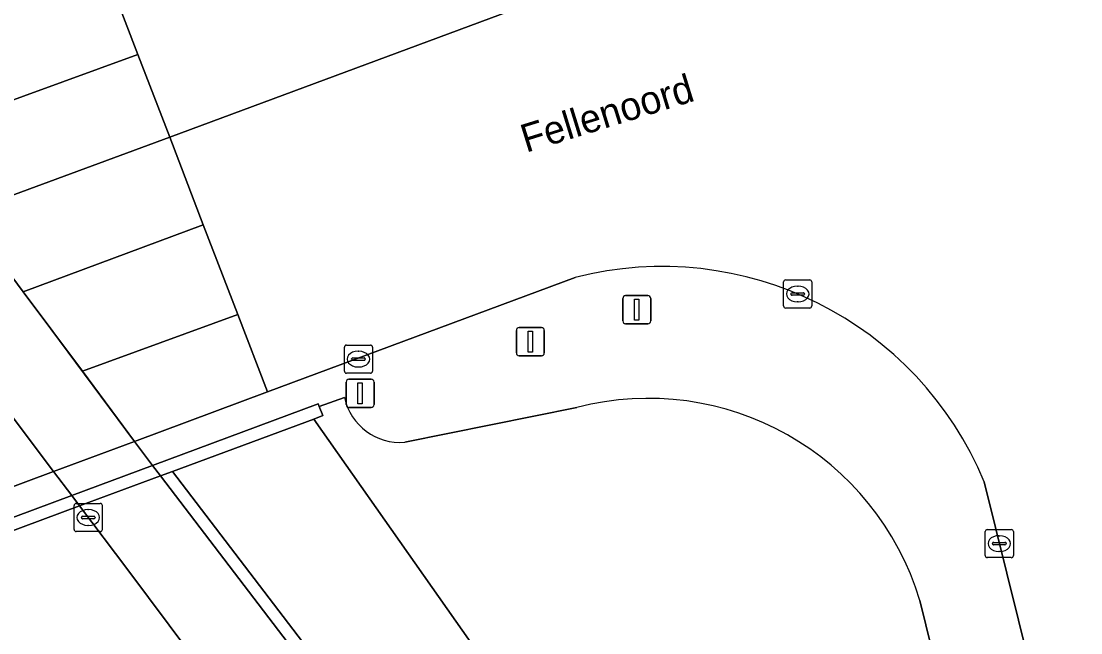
# Model space of a CAD drawing. Extents: x 160806 to 161707, y 383696 to 384148.
# Drawn here: x 160918.71 to 160956.33, y 383784.83 to 383806.57 of the extents above; entities that cross this region are included whole.
import ezdxf

# ---------------------------------------------------------------- set-up
doc = ezdxf.new("R2010")
doc.units = 0
for name, color, linetype in [('IMGEO_Fietspad_open', 7, 'Continuous'), ('IMGEO_Groenvoorziening', 7, 'Continuous'), ('IMGEO_Kolk', 7, 'Continuous'), ('IMGEO_Lichtmast', 7, 'Continuous'), ('IMGEO_Muur', 7, 'Continuous'), ('IMGEO_Openbare_ruimte_label', 7, 'Continuous'), ('IMGEO_Portaal', 7, 'Continuous'), ('IMGEO_Rijbaan_lokaal_gesloten', 7, 'Continuous'), ('IMGEO_Tunneldeel', 7, 'Continuous'), ('IMGEO_Verkeersregelinstallatiepaal', 7, 'Continuous'), ('IMGEO_Voetpad_open', 7, 'Continuous')]:
    doc.layers.add(name, color=color, linetype=linetype)

msp = doc.modelspace()

# ---------------------------------------------------------------- linework, layer by layer
at = {"layer": 'IMGEO_Fietspad_open'}
msp.add_lwpolyline([(160913.472, 383786.627), (160920.782, 383789.342), (160920.504, 383789.712), (160919.859, 383790.567), (160917.92, 383793.142), (160915.876, 383795.857), (160913.746, 383798.685), (160911.782, 383801.293), (160909.683, 383804.08), (160909.041, 383804.933), (160908.755, 383805.313), (160901.429, 383802.588), (160901.723, 383802.199), (160902.389, 383801.315), (160904.459, 383798.572), (160906.422, 383795.971), (160908.56, 383793.137), (160910.634, 383790.388), (160912.551, 383787.848), (160913.199, 383786.989)], close=True, dxfattribs=at)
at = {"layer": 'IMGEO_Groenvoorziening'}
for points in [[(160930.187, 383793.193), (160929.293, 383792.872), (160929.426, 383792.553), (160929.1, 383792.432), (160936.888, 383781.34), (160944.875, 383771.933), (160953.439, 383774.547), (160950.615, 383785.978)], [(160938.441, 383792.84), (160932.332, 383791.606)], [(160936.888, 383781.34), (160929.1, 383792.432), (160924.086, 383790.569), (160937.932, 383772.405)]]:
    msp.add_lwpolyline(points, dxfattribs=at)
for centre, radius, start, end in [((160932.17, 383793.63), 2.031, 192.4361, 274.5714), ((160940.977, 383783.109), 10.056, 16.5778, 104.6057)]:
    msp.add_arc(centre, radius, start, end, dxfattribs=at)
at = {"layer": 'IMGEO_Kolk'}
for p, q in [((160945.856, 383797.376), (160946.708, 383797.376)), ((160945.781, 383796.45), (160945.781, 383797.302)), ((160946.269, 383797.156), (160946.294, 383797.156)), ((160946.782, 383797.302), (160946.782, 383796.45)), ((160946.04, 383796.87), (160946.04, 383796.882)), ((160946.478, 383796.833), (160946.08, 383796.833)), ((160946.083, 383796.919), (160946.481, 383796.919)), ((160946.292, 383796.596), (160946.267, 383796.596)), ((160946.524, 383796.882), (160946.524, 383796.87)), ((160946.708, 383796.376), (160945.856, 383796.376)), ((160930.185, 383794.135), (160930.185, 383794.987)), ((160930.26, 383795.061), (160931.112, 383795.061)), ((160930.673, 383794.841), (160930.698, 383794.841)), ((160931.186, 383794.987), (160931.186, 383794.135)), ((160930.444, 383794.555), (160930.444, 383794.567)), ((160930.882, 383794.518), (160930.484, 383794.518)), ((160930.487, 383794.604), (160930.885, 383794.604)), ((160930.928, 383794.567), (160930.928, 383794.555)), ((160931.112, 383794.061), (160930.26, 383794.061)), ((160930.696, 383794.281), (160930.671, 383794.281)), ((160920.666, 383789.432), (160921.518, 383789.432)), ((160920.591, 383788.506), (160920.591, 383789.358)), ((160921.079, 383789.212), (160921.104, 383789.212)), ((160921.592, 383789.358), (160921.592, 383788.506)), ((160920.85, 383788.926), (160920.85, 383788.938)), ((160921.288, 383788.889), (160920.89, 383788.889)), ((160920.893, 383788.975), (160921.291, 383788.975)), ((160921.334, 383788.938), (160921.334, 383788.926)), ((160921.518, 383788.432), (160920.666, 383788.432)), ((160921.102, 383788.652), (160921.077, 383788.652)), ((160952.938, 383787.58), (160952.938, 383788.432)), ((160953.013, 383788.506), (160953.865, 383788.506)), ((160953.939, 383788.432), (160953.939, 383787.58)), ((160953.197, 383788), (160953.197, 383788.012)), ((160953.635, 383787.963), (160953.237, 383787.963)), ((160953.24, 383788.049), (160953.638, 383788.049)), ((160953.426, 383788.286), (160953.451, 383788.286)), ((160953.681, 383788.012), (160953.681, 383788)), ((160953.449, 383787.726), (160953.424, 383787.726)), ((160953.865, 383787.506), (160953.013, 383787.506))]:
    msp.add_line(p, q, dxfattribs=at)
for points in [[(160945.856, 383797.376), (160946.708, 383797.376)], [(160945.781, 383796.45), (160945.781, 383797.302)], [(160946.782, 383797.302), (160946.782, 383796.45)], [(160946.708, 383796.376), (160945.856, 383796.376)], [(160930.185, 383794.135), (160930.185, 383794.987)], [(160930.26, 383795.061), (160931.112, 383795.061)], [(160931.186, 383794.987), (160931.186, 383794.135)], [(160931.112, 383794.061), (160930.26, 383794.061)], [(160920.666, 383789.432), (160921.518, 383789.432)], [(160920.591, 383788.506), (160920.591, 383789.358)], [(160921.592, 383789.358), (160921.592, 383788.506)], [(160921.518, 383788.432), (160920.666, 383788.432)], [(160952.938, 383787.58), (160952.938, 383788.432)], [(160953.013, 383788.506), (160953.865, 383788.506)], [(160953.939, 383788.432), (160953.939, 383787.58)], [(160953.865, 383787.506), (160953.013, 383787.506)]]:
    msp.add_lwpolyline(points, dxfattribs=at)
for centre, radius, start, end in [((160945.858, 383797.3), 0.0765, 91.552, 178.448), ((160945.858, 383797.3), 0.0765, 91.552, 178.448), ((160946.706, 383797.3), 0.0765, 1.552, 88.448), ((160946.706, 383797.3), 0.0765, 1.552, 88.448), ((160946.08, 383796.879), 0.0403, 85.8775, 175.7526), ((160946.077, 383796.869), 0.0366, 178.938, 274.7102), ((160946.481, 383796.876), 0.043, 264.8664, 352.4533), ((160946.485, 383796.881), 0.0386, 1.7309, 96.639), ((160945.858, 383796.452), 0.0765, 181.552, 268.448), ((160945.858, 383796.452), 0.0765, 181.552, 268.448), ((160946.706, 383796.452), 0.0765, 271.552, 358.448), ((160946.706, 383796.452), 0.0765, 271.552, 358.448), ((160930.262, 383794.985), 0.0765, 91.552, 178.448), ((160930.262, 383794.985), 0.0765, 91.552, 178.448), ((160931.11, 383794.985), 0.0765, 1.552, 88.448), ((160931.11, 383794.985), 0.0765, 1.552, 88.448), ((160930.484, 383794.564), 0.0403, 85.8775, 175.7526), ((160930.481, 383794.554), 0.0366, 178.938, 274.7102), ((160930.885, 383794.561), 0.043, 264.8664, 352.4533), ((160930.889, 383794.566), 0.0386, 1.7309, 96.639), ((160930.262, 383794.137), 0.0765, 181.552, 268.448), ((160930.262, 383794.137), 0.0765, 181.552, 268.448), ((160931.11, 383794.137), 0.0765, 271.552, 358.448), ((160931.11, 383794.137), 0.0765, 271.552, 358.448), ((160920.668, 383789.356), 0.0765, 91.552, 178.448), ((160920.668, 383789.356), 0.0765, 91.552, 178.448), ((160921.516, 383789.356), 0.0765, 1.552, 88.448), ((160921.516, 383789.356), 0.0765, 1.552, 88.448), ((160920.89, 383788.935), 0.0403, 85.8775, 175.7526), ((160920.887, 383788.925), 0.0366, 178.938, 274.7102), ((160921.291, 383788.932), 0.043, 264.8664, 352.4533), ((160921.295, 383788.937), 0.0386, 1.7309, 96.639), ((160920.668, 383788.508), 0.0765, 181.552, 268.448), ((160920.668, 383788.508), 0.0765, 181.552, 268.448), ((160921.516, 383788.508), 0.0765, 271.552, 358.448), ((160921.516, 383788.508), 0.0765, 271.552, 358.448), ((160953.015, 383788.43), 0.0765, 91.552, 178.448), ((160953.015, 383788.43), 0.0765, 91.552, 178.448), ((160953.863, 383788.43), 0.0765, 1.552, 88.448), ((160953.863, 383788.43), 0.0765, 1.552, 88.448), ((160953.237, 383788.009), 0.0403, 85.8775, 175.7526), ((160953.234, 383787.999), 0.0366, 178.938, 274.7102), ((160953.638, 383788.006), 0.043, 264.8664, 352.4533), ((160953.642, 383788.011), 0.0386, 1.7309, 96.639), ((160953.015, 383787.582), 0.0765, 181.552, 268.448), ((160953.015, 383787.582), 0.0765, 181.552, 268.448), ((160953.863, 383787.582), 0.0765, 271.552, 358.448), ((160953.863, 383787.582), 0.0765, 271.552, 358.448)]:
    msp.add_arc(centre, radius, start, end, dxfattribs=at)
for centre, major_axis, ratio, start_param, end_param in [((160946.268, 383796.876), (-0.387, 0.002), 0.722429, 4.712389, 7.853982), ((160946.293, 383796.876), (-0.39, 0.002), 0.717154, 1.570796, 4.712389), ((160930.672, 383794.561), (-0.387, 0.002), 0.722429, 4.712389, 7.853982), ((160930.697, 383794.561), (-0.39, 0.002), 0.717154, 1.570796, 4.712389), ((160921.078, 383788.932), (-0.387, 0.002), 0.722429, 4.712389, 7.853982), ((160921.103, 383788.932), (-0.39, 0.002), 0.717154, 1.570796, 4.712389), ((160953.425, 383788.006), (-0.387, 0.002), 0.722429, 4.712389, 7.853982), ((160953.45, 383788.006), (-0.39, 0.002), 0.717154, 1.570796, 4.712389)]:
    msp.add_ellipse(centre, major_axis=major_axis, ratio=ratio, start_param=start_param, end_param=end_param, dxfattribs=at)
at = {"layer": 'IMGEO_Lichtmast'}
for p, q in [((160936.293, 383794.781), (160936.293, 383795.581)), ((160936.293, 383795.581), (160936.293, 383794.781)), ((160936.393, 383795.681), (160937.183, 383795.681)), ((160937.183, 383795.681), (160936.393, 383795.681)), ((160937.283, 383795.581), (160937.283, 383794.781)), ((160937.283, 383794.781), (160937.283, 383795.581)), ((160937.183, 383794.681), (160936.393, 383794.681)), ((160936.393, 383794.681), (160937.183, 383794.681))]:
    msp.add_line(p, q, dxfattribs=at)
msp.add_lwpolyline([(160936.713, 383795.556), (160936.863, 383795.556), (160936.863, 383794.806), (160936.713, 383794.806), (160936.713, 383795.556)], dxfattribs=at)
for centre, start, end in [((160936.393, 383795.581), 90, 180), ((160936.393, 383795.581), 90, 180), ((160937.183, 383795.581), 0, 90), ((160937.183, 383795.581), 360, 90), ((160936.393, 383794.781), 180, 270), ((160936.393, 383794.781), 180, 270), ((160937.183, 383794.781), 270, 0), ((160937.183, 383794.781), 270, 0)]:
    msp.add_arc(centre, 0.1, start, end, dxfattribs=at)
at = {"layer": 'IMGEO_Muur'}
for points in [[(160929.1, 383792.432), (160929.426, 383792.553), (160929.293, 383792.872), (160929.252, 383792.972), (160923.377, 383790.783), (160923.655, 383790.409), (160924.086, 383790.569)], [(160920.782, 383789.342), (160923.655, 383790.409), (160923.377, 383790.783), (160920.504, 383789.712), (160913.199, 383786.989), (160911.988, 383786.538), (160912.261, 383786.177), (160913.472, 383786.627)]]:
    msp.add_lwpolyline(points, close=True, dxfattribs=at)
msp.add_lwpolyline([(160937.932, 383772.405), (160924.086, 383790.569), (160923.655, 383790.409), (160937.594, 383772.128)], dxfattribs=at)
at = {"layer": 'IMGEO_Portaal'}
for p, q in [((160940.071, 383795.917), (160940.071, 383796.717)), ((160940.071, 383796.717), (160940.071, 383795.917)), ((160940.171, 383796.817), (160940.961, 383796.817)), ((160940.961, 383796.817), (160940.171, 383796.817)), ((160941.061, 383796.717), (160941.061, 383795.917)), ((160941.061, 383795.917), (160941.061, 383796.717)), ((160940.961, 383795.817), (160940.171, 383795.817)), ((160940.171, 383795.817), (160940.961, 383795.817))]:
    msp.add_line(p, q, dxfattribs=at)
msp.add_lwpolyline([(160940.491, 383796.692), (160940.641, 383796.692), (160940.641, 383795.942), (160940.491, 383795.942), (160940.491, 383796.692)], dxfattribs=at)
for centre, start, end in [((160940.171, 383796.717), 90, 180), ((160940.171, 383796.717), 90, 180), ((160940.961, 383796.717), 0, 90), ((160940.961, 383796.717), 360, 90), ((160940.171, 383795.917), 180, 270), ((160940.171, 383795.917), 180, 270), ((160940.961, 383795.917), 270, 0), ((160940.961, 383795.917), 270, 0)]:
    msp.add_arc(centre, 0.1, start, end, dxfattribs=at)
at = {"layer": 'IMGEO_Rijbaan_lokaal_gesloten'}
for points in [[(160969.022, 383808.791), (160967.931, 383811.718), (160966.768, 383814.836), (160965.623, 383817.907), (160957.325, 383814.835), (160923.983, 383802.443), (160925.177, 383799.334), (160926.402, 383796.144), (160927.458, 383793.395), (160938.382, 383797.46)], [(160922.883, 383809.085), (160921.617, 383808.606), (160922.851, 383805.392), (160923.983, 383802.443), (160957.325, 383814.835)], [(160952.902, 383790.2), (160956.543, 383775.501), (160966.145, 383778.487), (160961.63, 383796.537)]]:
    msp.add_lwpolyline(points, dxfattribs=at)
for points in [[(160921.617, 383808.606), (160917.962, 383807.222), (160912.65, 383805.205), (160914.718, 383802.425), (160922.851, 383805.392)], [(160923.983, 383802.443), (160922.851, 383805.392), (160914.718, 383802.425), (160916.701, 383799.758)], [(160918.784, 383796.957), (160916.701, 383799.758), (160914.718, 383802.425), (160912.65, 383805.205), (160909.683, 383804.08), (160902.389, 383801.315), (160901.15, 383800.846), (160903.193, 383798.148), (160905.196, 383795.504), (160907.295, 383792.732), (160909.438, 383789.903), (160911.337, 383787.396), (160912.551, 383787.848), (160919.859, 383790.567), (160922.74, 383791.639), (160920.882, 383794.138)], [(160923.983, 383802.443), (160916.701, 383799.758), (160918.784, 383796.957), (160925.177, 383799.334)], [(160926.402, 383796.144), (160925.177, 383799.334), (160918.784, 383796.957), (160920.882, 383794.138)], [(160927.458, 383793.395), (160926.402, 383796.144), (160920.882, 383794.138), (160922.74, 383791.639)], [(160922.492, 383787.071), (160920.782, 383789.342), (160913.472, 383786.627), (160926.2, 383769.556), (160929.425, 383765.273), (160936.499, 383768.375), (160933.47, 383772.374)]]:
    msp.add_lwpolyline(points, close=True, dxfattribs=at)
msp.add_arc((160941.467, 383785.48), 12.371, 22.4294, 104.4404, dxfattribs=at)
at = {"layer": 'IMGEO_Tunneldeel'}
msp.add_lwpolyline([(160912.65, 383805.205), (160912.023, 383806.047), (160911.742, 383806.425), (160908.755, 383805.313), (160901.429, 383802.588), (160900.182, 383802.124), (160900.478, 383801.734), (160901.15, 383800.846), (160911.337, 383787.396), (160911.988, 383786.538), (160912.261, 383786.177), (160913.472, 383786.627), (160920.782, 383789.342), (160923.655, 383790.409), (160923.377, 383790.783), (160922.74, 383791.639)], close=True, dxfattribs=at)
at = {"layer": 'IMGEO_Verkeersregelinstallatiepaal'}
for p, q in [((160930.248, 383792.945), (160930.248, 383793.745)), ((160930.248, 383793.745), (160930.248, 383792.945)), ((160930.348, 383793.845), (160931.138, 383793.845)), ((160931.138, 383793.845), (160930.348, 383793.845)), ((160931.238, 383793.745), (160931.238, 383792.945)), ((160931.238, 383792.945), (160931.238, 383793.745)), ((160931.138, 383792.845), (160930.348, 383792.845)), ((160930.348, 383792.845), (160931.138, 383792.845))]:
    msp.add_line(p, q, dxfattribs=at)
msp.add_lwpolyline([(160930.668, 383793.72), (160930.818, 383793.72), (160930.818, 383792.97), (160930.668, 383792.97), (160930.668, 383793.72)], dxfattribs=at)
for centre, start, end in [((160930.348, 383793.745), 90, 180), ((160930.348, 383793.745), 90, 180), ((160931.138, 383793.745), 0, 90), ((160931.138, 383793.745), 360, 90), ((160930.348, 383792.945), 180, 270), ((160930.348, 383792.945), 180, 270), ((160931.138, 383792.945), 270, 0), ((160931.138, 383792.945), 270, 0)]:
    msp.add_arc(centre, 0.1, start, end, dxfattribs=at)
at = {"layer": 'IMGEO_Voetpad_open'}
for points in [[(160920.782, 383789.342), (160923.655, 383790.409), (160923.377, 383790.783), (160922.74, 383791.639), (160912.65, 383805.205), (160912.023, 383806.047), (160911.742, 383806.425), (160908.755, 383805.313), (160909.041, 383804.933), (160909.683, 383804.08), (160911.782, 383801.293), (160913.746, 383798.685), (160915.876, 383795.857), (160917.92, 383793.142), (160919.859, 383790.567), (160920.504, 383789.712)], [(160920.504, 383789.712), (160923.377, 383790.783), (160922.74, 383791.639), (160919.859, 383790.567), (160912.551, 383787.848), (160911.337, 383787.396), (160911.988, 383786.538), (160913.199, 383786.989)]]:
    msp.add_lwpolyline(points, close=True, dxfattribs=at)
for points in [[(160938.382, 383797.46), (160927.458, 383793.395), (160922.74, 383791.639), (160923.377, 383790.783), (160929.252, 383792.972), (160929.293, 383792.872), (160930.187, 383793.193)], [(160932.332, 383791.606), (160938.441, 383792.84)], [(160923.655, 383790.409), (160920.782, 383789.342), (160922.492, 383787.071), (160933.47, 383772.374), (160936.499, 383768.375)], [(160937.594, 383772.128), (160923.655, 383790.409)], [(160950.615, 383785.978), (160953.439, 383774.547), (160955.438, 383775.157), (160956.543, 383775.501), (160952.902, 383790.2)]]:
    msp.add_lwpolyline(points, dxfattribs=at)
for centre, radius, start, end in [((160941.467, 383785.48), 12.371, 22.4294, 104.4404), ((160932.17, 383793.63), 2.031, 192.4361, 274.5714), ((160940.977, 383783.109), 10.056, 16.5778, 104.6057)]:
    msp.add_arc(centre, radius, start, end, dxfattribs=at)

# ---------------------------------------------------------------- texts
at = {"layer": 'IMGEO_Openbare_ruimte_label'}
msp.add_text('Fellenoord', height=1, rotation=17.149, dxfattribs=at).set_placement((160936.636, 383801.891))

doc.saveas('drawing.dxf')
